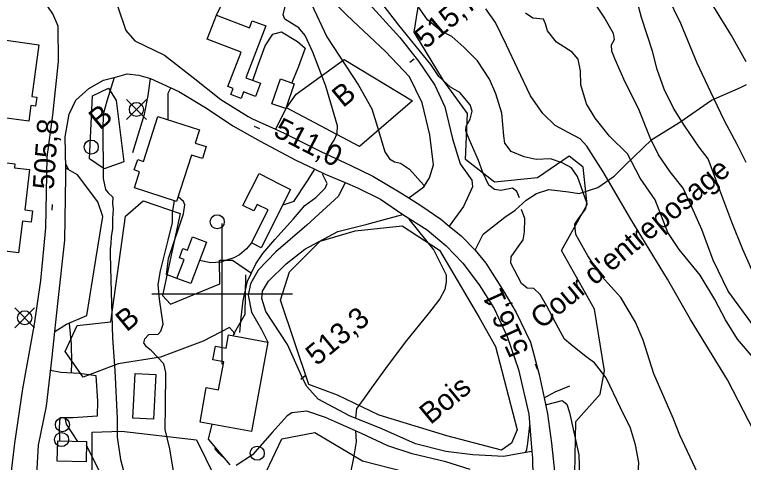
# Model space of a CAD drawing. Extents: x 347059 to 352153, y 6073752 to 6078601.
# Drawn here: x 349755.8 to 349911.2, y 6077664.1 to 6077759.6 of the extents above; entities that cross this region are included whole.
import ezdxf

# ---------------------------------------------------------------- set-up
doc = ezdxf.new("R2010")
doc.units = 0
for name, color, linetype in [('Level 1', 7, 'Continuous'), ('Level 19', 7, 'Continuous'), ('Level 2', 7, 'Continuous'), ('Level 21', 7, 'Continuous'), ('Level 22', 7, 'Continuous'), ('Level 3', 7, 'Continuous'), ('Level 31', 7, 'Continuous'), ('Level 36', 7, 'Continuous'), ('Level 44', 7, 'Continuous'), ('Level 57', 7, 'Continuous'), ('Level 61', 7, 'Continuous')]:
    doc.layers.add(name, color=color, linetype=linetype)

msp = doc.modelspace()

# ---------------------------------------------------------------- linework, layer by layer
at = {"layer": 'Level 1'}
for points in [[(349883.67, 6077721.9), (349881.3, 6077726.04), (349877.81, 6077731.52), (349876.36, 6077733.11), (349873.78, 6077734.43), (349871.07, 6077735.9), (349868.39, 6077738.47), (349865.77, 6077742.27), (349862.97, 6077748.05), (349860.69, 6077753.06), (349858.31, 6077757.85), (349856.26, 6077760.8)], [(349911.73, 6077749.52), (349908.65, 6077755.14), (349904.89, 6077761.25)], [(349788.49, 6077737.06), (349788.5, 6077742.84), (349789.06, 6077743.98)], [(349945.69, 6077562.71), (349948.99, 6077561.97), (349951.73, 6077562.89), (349953.95, 6077564.58), (349954.94, 6077566.46), (349954.15, 6077568.06), (349952.24, 6077571), (349949.53, 6077573.29), (349947.71, 6077577.1), (349946.59, 6077580.7), (349943.74, 6077594.8), (349936.94, 6077616.55), (349933.48, 6077627.5), (349929.44, 6077635.58), (349923.28, 6077650.41), (349915.75, 6077666.24), (349907.75, 6077681.67), (349899.86, 6077694.54), (349895, 6077703.13), (349887.18, 6077715.91), (349883.67, 6077721.9)], [(349790.29, 6077658.26), (349788.87, 6077666.96), (349787.87, 6077671.08), (349787.93, 6077676.06), (349788.05, 6077683.23), (349787.57, 6077685.1), (349784.97, 6077687.9), (349783.88, 6077688.73), (349783.3, 6077689.59), (349783.53, 6077690.45), (349784.43, 6077691.32), (349786.36, 6077691.44), (349786.93, 6077692.05), (349787.45, 6077693.54), (349786.65, 6077698.89), (349786.37, 6077701.99), (349786.88, 6077704.95), (349788.49, 6077711.47), (349789.44, 6077715.2), (349789.43, 6077717.32), (349789.8, 6077719.49), (349789.81, 6077719.85)]]:
    msp.add_lwpolyline(points, dxfattribs=at)
at = {"layer": 'Level 19'}
for points in [[(349839.8, 6077720.48), (349843.02, 6077722.81), (349844.25, 6077724.74), (349845.07, 6077727.52), (349844.33, 6077733.95), (349842.65, 6077740.78), (349839.99, 6077746.27), (349834.89, 6077751.73), (349827.89, 6077758.22), (349826.5, 6077759.6), (349823.84, 6077762.24), (349826.99, 6077766.62), (349828.64, 6077765), (349831.38, 6077761.83), (349837.88, 6077754.69), (349841.92, 6077749.61), (349845.38, 6077744.5), (349847.54, 6077739.87), (349849.18, 6077733.08), (349850.79, 6077727.76), (349853.29, 6077724.24), (349853.4, 6077722.83), (349851.52, 6077718.63), (349848.41, 6077714.48)], [(349798.79, 6077759.43), (349799.89, 6077761.64), (349796.32, 6077763.08)], [(349806.57, 6077745.55), (349807.57, 6077748.42), (349809.23, 6077752.92), (349810.8, 6077755.37), (349812.65, 6077755.87), (349816.07, 6077753.84), (349817.71, 6077752.43), (349816.33, 6077748.48), (349814.89, 6077745)], [(349780.96, 6077730.14), (349783.48, 6077738.35), (349784.28, 6077742.33), (349784.75, 6077745.93)], [(349780.96, 6077730.14), (349783.48, 6077738.35), (349784.28, 6077742.33), (349784.75, 6077745.93)], [(349813.58, 6077739.55), (349812.58, 6077737.51), (349811.4, 6077735.11)], [(349764.35, 6077692.02), (349766.82, 6077693.57), (349771.17, 6077695.41), (349773.12, 6077707.31), (349774.62, 6077716.5), (349773.5, 6077719.63), (349769.16, 6077725.43), (349766.69, 6077726.81)], [(349815.28, 6077719.73), (349818.23, 6077724.09), (349819.77, 6077726.61)], [(349826.24, 6077723.79), (349824.86, 6077720.82), (349818.11, 6077714.63), (349811.49, 6077709), (349807.71, 6077705.09), (349806.07, 6077702.12), (349805.57, 6077699.76), (349806.31, 6077696.1), (349808.44, 6077692.4), (349809.77, 6077689.74)], [(349790.39, 6077703.3), (349788.18, 6077704.15), (349788.6, 6077707.53), (349791.78, 6077717.07), (349792.04, 6077719.02), (349791.77, 6077719.7), (349790.63, 6077720.72)], [(349815.28, 6077719.73), (349812.94, 6077718.91)], [(349866.08, 6077666.37), (349863.12, 6077665.92), (349860.1, 6077665.33), (349853.45, 6077665.67), (349847.69, 6077666.38), (349841.28, 6077668.04), (349834.06, 6077671.2), (349827.21, 6077674), (349820.47, 6077677.57), (349818.05, 6077680.27), (349817.26, 6077681.93), (349813.98, 6077689.24), (349809.33, 6077696.22), (349808.48, 6077699.04), (349808.61, 6077700.58), (349809.9, 6077702.71), (349813.7, 6077706.42), (349817.69, 6077709.55), (349824.72, 6077713.34), (349830.93, 6077714.88), (349835.62, 6077716.18), (349838.53, 6077716.91)], [(349806.28, 6077710.87), (349805.22, 6077709.61), (349803.72, 6077708.34), (349802.52, 6077707.71), (349800.75, 6077707.12), (349799.77, 6077706.75), (349797.63, 6077706.61), (349795.2, 6077707.1)], [(349765.39, 6077668.64), (349765.32, 6077671.53), (349765.51, 6077673.66), (349768.18, 6077673.63), (349773.47, 6077674), (349773.55, 6077677.16), (349773.13, 6077682.56), (349769.55, 6077683.03), (349765.62, 6077683.21), (349763.44, 6077683.69)], [(349868.66, 6077677.86), (349871.05, 6077679.11), (349874.14, 6077680.43)], [(349852.89, 6077662.53), (349847.69, 6077664.17), (349840.55, 6077665.89), (349835.36, 6077667.61), (349829.77, 6077670.26), (349822.03, 6077673.68), (349818.07, 6077675), (349814.9, 6077674.67), (349813.86, 6077674.02), (349810.7, 6077670.47), (349806.52, 6077665.69), (349803.02, 6077663.42)], [(349801.72, 6077663.54), (349797.13, 6077669), (349797.92, 6077672.2)]]:
    msp.add_lwpolyline(points, dxfattribs=at)
at = {"layer": 'Level 2'}
for points in [[(349903.66, 6077728.83), (349901.72, 6077731.33), (349898.53, 6077735.96), (349896.27, 6077739.64), (349894.26, 6077743.66), (349892.78, 6077747.85), (349891.78, 6077751.77), (349889.43, 6077758.94), (349888, 6077764.36)], [(349909.82, 6077731.84), (349907.06, 6077737.08), (349904.22, 6077743.05), (349901.34, 6077749.24), (349897.81, 6077757.66), (349894.91, 6077763.7)], [(349813.03, 6077759.49), (349813.79, 6077762.79)], [(349898.33, 6077722.54), (349895.54, 6077726.06), (349893.05, 6077729.69), (349891.28, 6077733.26), (349888.84, 6077739.57), (349885.96, 6077745.13), (349883.81, 6077749.96), (349883.11, 6077751.77), (349883.03, 6077753.15), (349883.72, 6077754.25), (349883.48, 6077755.51), (349881.49, 6077759.02), (349879.2, 6077762.42)], [(349819.04, 6077761.95), (349822.38, 6077754.86), (349829.07, 6077744.55), (349831.95, 6077739.47), (349833.18, 6077735.56), (349834.72, 6077730.3), (349835.68, 6077728.83), (349836.78, 6077728.15), (349838.08, 6077727.89), (349839.95, 6077726.63), (349842.99, 6077723.28), (349843.11, 6077722.94)], [(349863.46, 6077720.47), (349862.88, 6077721.85), (349861.92, 6077722.52), (349859.45, 6077722.08), (349858.08, 6077722.28), (349856.92, 6077723.18), (349855.58, 6077725.93), (349854.66, 6077728.49), (349852.68, 6077732.98), (349851.98, 6077734.79), (349852.08, 6077735.8), (349852.88, 6077737.27), (349853.35, 6077738.98), (349852.89, 6077740.33), (349850.73, 6077742.93), (349848.71, 6077744.06), (349846.22, 6077746.4), (349844.5, 6077748.96), (349837.69, 6077757.3), (349834.57, 6077761.37)], [(349885.02, 6077699.21), (349880.93, 6077703.81), (349877.99, 6077708.15), (349875.43, 6077712.68), (349875.2, 6077714.89), (349876.24, 6077716.4), (349877.58, 6077718.18), (349877.78, 6077719.4), (349875.77, 6077725.05), (349874.49, 6077726.91), (349872.54, 6077727.96), (349870.06, 6077728.83), (349866.96, 6077728.67), (349864.45, 6077729.26), (349861.63, 6077730.38), (349860.27, 6077732.18), (349860.06, 6077733.73), (349859.66, 6077738.58), (349858.38, 6077742.7), (349857, 6077745.81), (349854.45, 6077749.68), (349851.59, 6077752.63), (349849.03, 6077754.9), (349846.66, 6077756.13), (349843.81, 6077758.42), (349841.82, 6077761.29)], [(349823.92, 6077732.76), (349824.58, 6077734.24), (349824.59, 6077735.85), (349822.12, 6077744.34), (349819.38, 6077751.54), (349817.74, 6077755.12), (349816.36, 6077756.78), (349813.38, 6077758.58), (349813.03, 6077759.49)], [(349892.34, 6077720.07), (349889.14, 6077724.72), (349886.43, 6077729.9), (349882.64, 6077733.65), (349879.58, 6077737.49), (349877.69, 6077740.56), (349876.48, 6077744.59), (349876.41, 6077747.58), (349875.93, 6077750.09), (349874.69, 6077751.59), (349871.31, 6077753.7), (349869.43, 6077756.12), (349868.99, 6077757.61), (349868.58, 6077758.59), (349866.26, 6077758.8), (349864.69, 6077759.88)], [(349777.01, 6077746.16), (349775.42, 6077741.1), (349774.72, 6077738.52), (349774.62, 6077736.04), (349774.64, 6077724.63), (349775.12, 6077722.29), (349775.72, 6077721.59), (349776.72, 6077720.61), (349776.62, 6077719.3), (349776.77, 6077718.05), (349776.63, 6077716.09), (349776.63, 6077715.02), (349776.63, 6077713.95), (349776.34, 6077712.16), (349776.32, 6077710.77), (349776.14, 6077709.54), (349776.15, 6077708.47), (349776.28, 6077702.94), (349776.68, 6077690.58), (349777.17, 6077683.64), (349777.64, 6077673.47), (349777.61, 6077669.44), (349778.32, 6077664.68), (349779.61, 6077659.87)], [(349822.51, 6077729.73), (349822.84, 6077731.14), (349823.92, 6077732.76)], [(349911.77, 6077728.05), (349909.82, 6077731.84)], [(349914.12, 6077702.6), (349911.08, 6077709.47), (349908.74, 6077715.33), (349905.97, 6077722.68), (349903.66, 6077728.83)], [(349767.35, 6077726.44), (349766.68, 6077727.69)], [(349803.81, 6077691.78), (349804.06, 6077694.94), (349804.5, 6077698.63), (349805.42, 6077702.72), (349807.18, 6077706.44), (349808.73, 6077708.65), (349811.23, 6077711.64), (349815.27, 6077716.04), (349817.68, 6077718.83), (349819.99, 6077720.6), (349822.02, 6077722.54), (349822.41, 6077723.53), (349821.49, 6077725.41), (349821.57, 6077725.75)], [(349913.51, 6077692.88), (349907.92, 6077700.57), (349904.7, 6077707.17), (349902.28, 6077713.77), (349900.2, 6077718.53), (349898.33, 6077722.54)], [(349913.23, 6077686.43), (349909.95, 6077690.36), (349907.36, 6077694.45), (349905.08, 6077698.8), (349901.94, 6077704.02), (349897.51, 6077709.5), (349895.08, 6077713.07), (349892.34, 6077720.07)], [(349874.41, 6077689.21), (349873.06, 6077690.35), (349871.75, 6077692.73), (349869.22, 6077697.56), (349867.83, 6077699.87), (349866.49, 6077701.16), (349865.1, 6077701.21), (349863.87, 6077702.19), (349861.59, 6077706.56), (349861.65, 6077707.94), (349862.76, 6077709.52), (349864.21, 6077711.51), (349864.53, 6077713.23), (349864.59, 6077716.08), (349863.87, 6077717.99)], [(349839.93, 6077716.04), (349839.85, 6077715.92), (349845.14, 6077709.35), (349847.78, 6077704.07), (349847.78, 6077702.61), (349847.54, 6077700.95), (349846.47, 6077698.99), (349844.27, 6077696.12), (349839.08, 6077689.71), (349834.85, 6077684.1), (349832.21, 6077680.46), (349829.98, 6077677.3), (349828.71, 6077675.58), (349828.43, 6077673.51)], [(349913.88, 6077611.14), (349911.15, 6077618.46), (349909.9, 6077622.08), (349908.8, 6077627.28), (349909.03, 6077630.4), (349909.99, 6077634.11), (349910.86, 6077636.95), (349910.33, 6077639.84), (349909.27, 6077644.68), (349906, 6077650.88), (349902.51, 6077659.43), (349897.6, 6077669.87), (349896.2, 6077673.49), (349892.07, 6077682.98), (349889.77, 6077690.11), (349888.17, 6077693.97), (349885.02, 6077699.21)], [(349767.87, 6077683.11), (349767.96, 6077685.44), (349767.89, 6077689.27), (349767.45, 6077693.72), (349767.44, 6077693.83)], [(349878.51, 6077646.05), (349880.27, 6077647.49), (349883, 6077650.54), (349886.29, 6077654.84), (349888.62, 6077659.01), (349888.89, 6077664.03), (349888.17, 6077667.82), (349887.12, 6077671.34), (349884.98, 6077675.7), (349881.94, 6077682.11), (349879.39, 6077685.33), (349877.68, 6077686.58), (349874.41, 6077689.21)], [(349868.98, 6077676.35), (349872.54, 6077677.26), (349873.52, 6077676.51), (349874.08, 6077674.7), (349876.05, 6077665.69), (349876.24, 6077660.93), (349876.5, 6077655.43), (349876.72, 6077649.49), (349877.3, 6077646.37), (349877.76, 6077645.82), (349878.51, 6077646.05)], [(349769.24, 6077668.5), (349766.87, 6077672.24), (349766.55, 6077673.65)], [(349864.7, 6077666.16), (349865, 6077666.83), (349865.18, 6077668.19), (349865.63, 6077671.96)], [(349828.43, 6077670.86), (349828.59, 6077668.43), (349828.03, 6077665.05), (349826.65, 6077658.45), (349826.39, 6077652.92), (349826.06, 6077643.59), (349825.58, 6077641.73), (349826.12, 6077639.78), (349827.07, 6077637.51), (349828.21, 6077634.19), (349828.17, 6077630.03), (349828.54, 6077621.95)], [(349772.65, 6077656.21), (349774, 6077659.25), (349774.22, 6077661.44), (349771.12, 6077667.77)], [(349800.86, 6077664.56), (349799.42, 6077665.94), (349798.55, 6077666.94), (349798.62, 6077667.23)]]:
    msp.add_lwpolyline(points, dxfattribs=at)
at = {"layer": 'Level 21'}
for points in [[(349755.05, 6077661.53), (349755.8, 6077668.21), (349757.51, 6077679.77), (349759.69, 6077691.58), (349759.98, 6077693.54), (349761.34, 6077702.85), (349762.4, 6077714.09), (349762.74, 6077729.18), (349763.93, 6077738.11), (349765.13, 6077749.54), (349765.05, 6077757.1), (349763.93, 6077759.71), (349762.83, 6077761.28), (349759.17, 6077763.94), (349751.97, 6077769.01), (349744.46, 6077774.28), (349741.35, 6077775.37), (349730.35, 6077777.49), (349725.37, 6077777.26), (349724.23, 6077777.2), (349722.43, 6077775.55), (349721.54, 6077771.91)], [(349777.69, 6077761.45), (349779.48, 6077756.16), (349781.38, 6077753.99), (349787.71, 6077750.93), (349793.84, 6077746.14), (349799.73, 6077741.44), (349805.6, 6077737.87), (349806.48, 6077737.33), (349811.4, 6077735.11), (349813.25, 6077734.28), (349821.08, 6077730.4), (349827.32, 6077727.44), (349832.13, 6077725.1), (349837.8, 6077721.74), (349839.8, 6077720.48), (349842.59, 6077718.71), (349846.67, 6077715.91), (349848.41, 6077714.48), (349850.96, 6077712.39), (349853.96, 6077709.35), (349856.28, 6077706.58), (349859.92, 6077700.72), (349862.72, 6077696.03), (349865.79, 6077689.7), (349867.63, 6077682.85), (349868.66, 6077677.86), (349869.37, 6077674.44), (349870.29, 6077668.17), (349871.12, 6077660.11)], [(349760.34, 6077659.03), (349760.86, 6077667.78), (349762.57, 6077676.09), (349763.77, 6077686.54), (349764.35, 6077692.02), (349764.98, 6077697.97), (349766.48, 6077711.47), (349766.73, 6077725.04), (349766.69, 6077726.81), (349766.56, 6077733.52), (349767.44, 6077738.33), (349768.85, 6077741.32), (349771.57, 6077743.83), (349774.71, 6077745.57), (349777.31, 6077746.24), (349779.75, 6077746.93), (349782.27, 6077746.64)], [(349782.27, 6077746.64), (349784.75, 6077745.93), (349790.81, 6077743.18), (349796.68, 6077739.6), (349802.28, 6077735.87), (349808.13, 6077732.58), (349815.71, 6077728.56), (349819.77, 6077726.61), (349821.98, 6077725.55), (349826.24, 6077723.79), (349828.87, 6077722.62), (349833.8, 6077720.22), (349838.53, 6077716.91), (349843.71, 6077713.68), (349847.77, 6077710.27), (349851.36, 6077706.53), (349854.83, 6077701.94), (349858.01, 6077696.9), (349860.82, 6077690.94), (349863.21, 6077683.89), (349865.43, 6077674.37), (349866.08, 6077666.37), (349866.19, 6077664.98), (349866.32, 6077657.15)]]:
    msp.add_lwpolyline(points, dxfattribs=at)
at = {"layer": 'Level 22'}
msp.add_lwpolyline([(349853.96, 6077709.35), (349855.69, 6077712.77), (349860.32, 6077716.36), (349862.49, 6077717.88), (349864.87, 6077720.03), (349867.03, 6077721.39), (349869.71, 6077722.29), (349873.89, 6077721.76), (349876.14, 6077721.4), (349880.15, 6077722.68), (349883.61, 6077725.13), (349885.92, 6077727.37), (349891.67, 6077732.94), (349897.65, 6077736.61), (349904.36, 6077741.35), (349910.56, 6077744.03), (349911.83, 6077744.68)], dxfattribs=at)
at = {"layer": 'Level 3'}
for p, q in [((349840.07, 6077749.39), (349840.99, 6077750.16)), ((349806.89, 6077735.81), (349807.96, 6077735.26)), ((349763.75, 6077717.86), (349763.83, 6077719.06)), ((349867.3, 6077683.92), (349866.81, 6077685.01)), ((349816.83, 6077681.8), (349817.75, 6077682.57))]:
    msp.add_line(p, q, dxfattribs=at)
at = {"layer": 'Level 31'}
for points in [[(349801.27, 6077744.24), (349804.08, 6077751.55), (349796.83, 6077754.33), (349798.79, 6077759.43), (349805.87, 6077756.72), (349806.46, 6077758.24), (349809.33, 6077757.14), (349805.1, 6077746.11), (349808.21, 6077744.92), (349807.14, 6077742.12), (349804.61, 6077743.08), (349804.08, 6077741.69), (349801.86, 6077742.55), (349802.35, 6077743.83), (349801.27, 6077744.24)], [(349760.95, 6077753.11), (349759.42, 6077742.1), (349760.51, 6077741.95), (349760.24, 6077740.06), (349759.25, 6077740.2), (349758.78, 6077736.82), (349749.23, 6077738.15), (349750.73, 6077748.92), (349749.78, 6077749.05), (349750.11, 6077751.4), (349750.94, 6077751.28), (349751.38, 6077754.44), (349760.95, 6077753.11)], [(349810.63, 6077740.56), (349812.44, 6077745.84), (349815.39, 6077744.83), (349813.58, 6077739.55), (349810.63, 6077740.56)], [(349794.28, 6077732.17), (349796.65, 6077731.41), (349795.83, 6077728.86), (349793.5, 6077729.61), (349790.29, 6077719.69), (349781.31, 6077722.6), (349782.43, 6077726.06), (349781.3, 6077726.43), (349782.03, 6077728.65), (349783.24, 6077728.26), (349786.34, 6077737.82), (349795.19, 6077734.96), (349794.28, 6077732.17)], [(349740.23, 6077729.63), (349755.84, 6077727.73), (349755.74, 6077726.92), (349758.97, 6077726.52), (349757.92, 6077717.92), (349759.57, 6077717.72), (349759.27, 6077715.32), (349757.43, 6077715.55), (349756.61, 6077708.79), (349753.69, 6077709.14), (349752.84, 6077702.23), (349736.95, 6077704.16), (349738.13, 6077713.88), (349733.21, 6077714.48), (349734.33, 6077723.7), (349739.43, 6077723.07), (349740.23, 6077729.63)], [(349804.44, 6077718.83), (349807.9, 6077725.66), (349812.47, 6077723.35), (349814.63, 6077722.25), (349808.33, 6077709.83), (349806.28, 6077710.87), (349809.85, 6077717.91), (349807.5, 6077719.1), (349806.8, 6077717.72), (349804.44, 6077718.83)], [(349796.7, 6077711.07), (349793.35, 6077702.19), (349790.39, 6077703.3), (349791.92, 6077707.34), (349790.9, 6077707.73), (349791.63, 6077709.68), (349792.61, 6077709.31), (349793.7, 6077712.2), (349796.7, 6077711.07)], [(349795.31, 6077672.68), (349796.65, 6077680.05), (349799.28, 6077679.57), (349800.37, 6077685.55), (349798.05, 6077685.97), (349798.58, 6077688.87), (349800.9, 6077688.44), (349801.41, 6077691.26), (349809.77, 6077689.74), (349806.3, 6077670.67), (349795.31, 6077672.68)], [(349785.87, 6077682.79), (349785.4, 6077673.31), (349781.01, 6077673.52), (349781.47, 6077683), (349785.87, 6077682.79)], [(349764.97, 6077668.65), (349771.11, 6077668.52), (349771.01, 6077664.19), (349764.88, 6077664.32), (349764.97, 6077668.65)]]:
    msp.add_lwpolyline(points, dxfattribs=at)
at = {"layer": 'Level 36'}
for p, q in [((349783.87, 6077737.22), (349779.64, 6077741.45)), ((349779.64, 6077737.22), (349783.87, 6077741.45)), ((349760.03, 6077692.79), (349755.8, 6077697.02)), ((349755.8, 6077692.79), (349760.03, 6077697.02))]:
    msp.add_line(p, q, dxfattribs=at)
for centre in [(349781.76, 6077739.34), (349772.12, 6077731.32), (349798.97, 6077715.39), (349757.92, 6077694.91), (349765.97, 6077672.12), (349765.78, 6077668.93), (349807.5, 6077666.02)]:
    msp.add_circle(centre, 1.5, dxfattribs=at)
at = {"layer": 'Level 44'}
for points in [[(349875.26, 6077661.72), (349875.42, 6077672.78), (349880.65, 6077678.66), (349881.58, 6077683.62), (349879.4, 6077696.74), (349872.38, 6077709.23), (349877.87, 6077719.07), (349877.03, 6077727.02), (349873.99, 6077729.4), (349867.25, 6077724.79), (349858.07, 6077723.81), (349851.91, 6077728.66), (349852.36, 6077738.47), (349847.21, 6077745.51), (349840.96, 6077755.82), (349842.76, 6077767.03)], [(349826.08, 6077749.98), (349840.6, 6077741.21), (349829.32, 6077731.45), (349813.76, 6077739.66), (349815.81, 6077742.58), (349826.08, 6077749.98)], [(349777.44, 6077741.22), (349779.08, 6077728.14), (349774.86, 6077726.7), (349771.77, 6077728.78), (349772.38, 6077742.24), (349775.8, 6077743.91), (349777.44, 6077741.22)], [(349804.99, 6077704.05), (349804.88, 6077695.6), (349802.39, 6077691.26), (349802.72, 6077691.54), (349801.62, 6077692.87), (349795.97, 6077689.93), (349786.85, 6077686.48), (349777.82, 6077685.07), (349770.37, 6077682.28), (349766.58, 6077687.7), (349769.12, 6077693.3), (349776.32, 6077694.06), (349779.44, 6077716.55), (349783.16, 6077719.83), (349791.11, 6077717.17), (349787.29, 6077699.67), (349789, 6077697.81), (349799.51, 6077702.12), (349799.47, 6077707.19), (349802.24, 6077707.22), (349806.3, 6077704.45)], [(349859.61, 6077666.67), (349847.93, 6077669.75), (349833.48, 6077674.14), (349824.62, 6077678.41), (349818.51, 6077680.7), (349812.46, 6077698.69), (349814.42, 6077704.74), (349820.95, 6077711.24), (349828.4, 6077713.45), (349838.44, 6077714.52), (349846.38, 6077709.34), (349854.82, 6077694.99), (349858.34, 6077688.81), (349862.96, 6077670.99), (349861.74, 6077668.16), (349859.61, 6077666.67)], [(349772.23, 6077654.05), (349772.28, 6077670.52), (349778.6, 6077670.7), (349794.56, 6077668.89), (349798.55, 6077660.8)], [(349807.39, 6077657.89), (349812.74, 6077669.07), (349819.81, 6077670.44), (349829.95, 6077664.38), (349847.72, 6077659.88)]]:
    msp.add_lwpolyline(points, dxfattribs=at)
at = {"layer": 'Level 61'}
for p, q in [((349800, 6077685), (349800, 6077715)), ((349785, 6077700), (349815, 6077700))]:
    msp.add_line(p, q, dxfattribs=at)

# ---------------------------------------------------------------- texts
at = {"layer": 'Level 3'}
for s, rotation, p in [('515,7', 39.62, (349843.43, 6077752.1)), ('511,0', 332.9019, (349810.71, 6077733.8)), ('505,8', 86.0048, (349764.1, 6077722.16)), ('516,1', 114.1967, (349865.58, 6077687.88)), ('513,3', 39.62, (349820.19, 6077684.52))]:
    msp.add_text(s, height=4.5, rotation=rotation, dxfattribs=at).set_placement(p)
at = {"layer": 'Level 44'}
for s, p in [('B', (349825.81, 6077739.58)), ('B', (349773.94, 6077734.81)), ('B', (349779.66, 6077691.77)), ('Bois', (349844.45, 6077672))]:
    msp.add_text(s, height=4.5, rotation=39.568, dxfattribs=at).set_placement(p)
at = {"layer": 'Level 57'}
msp.add_text("Cour d'entreposage", height=4.5, rotation=39.568, dxfattribs=at).set_placement((349868.11, 6077692.32))

doc.saveas('drawing.dxf')
